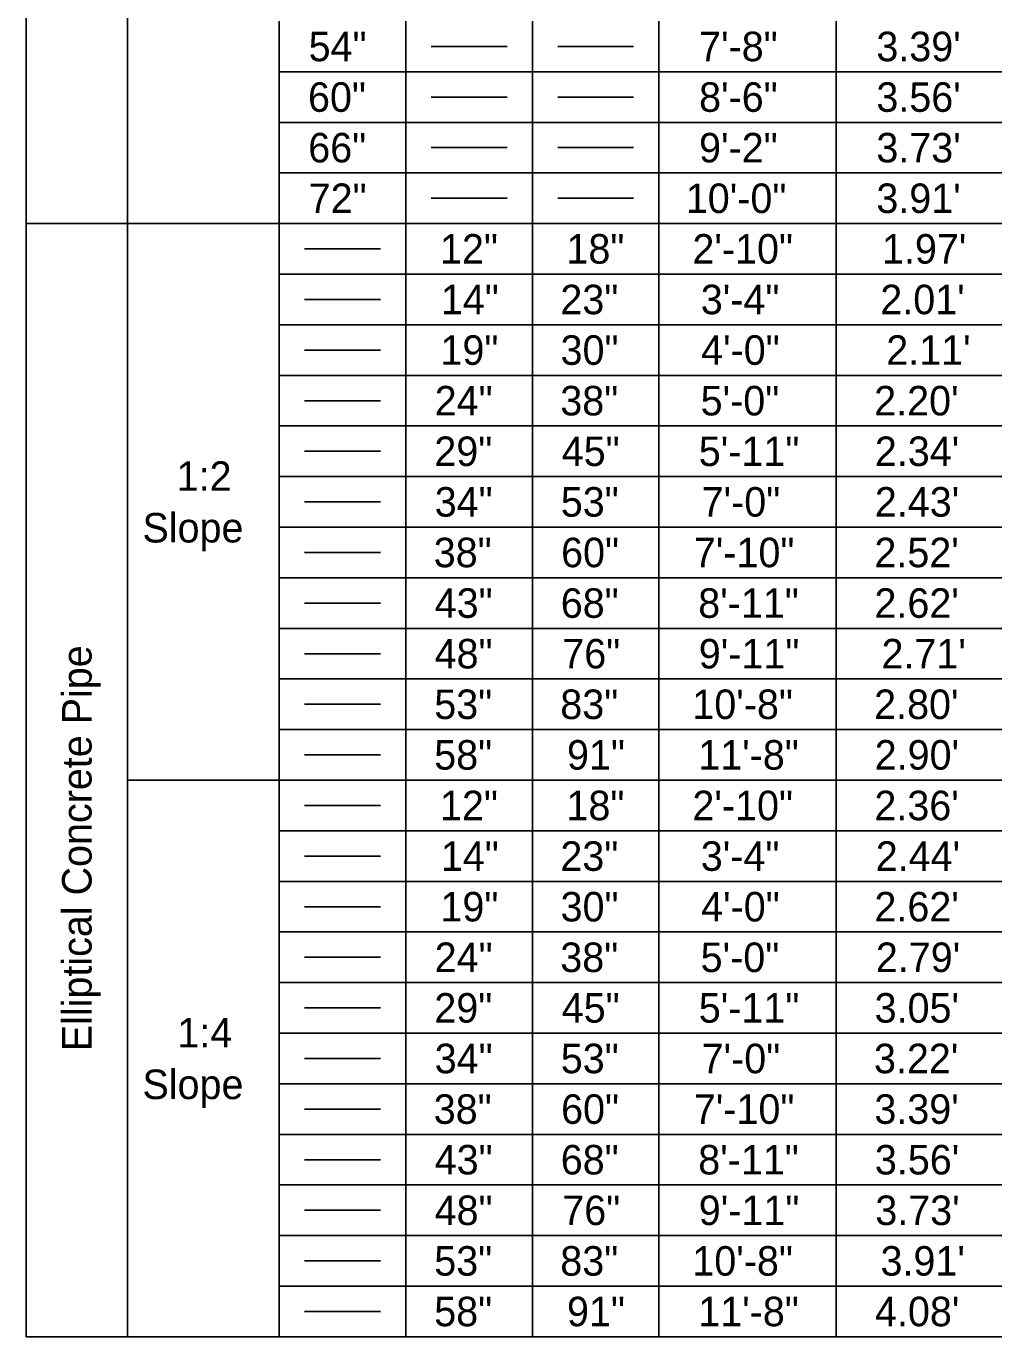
# Model space of a CAD drawing. Extents: x 1.7 to 14.6, y 0 to 8.4.
# Drawn here: x 1.7 to 3.994, y 2.19 to 5.298 of the extents above; entities that cross this region are included whole.
import ezdxf

# ---------------------------------------------------------------- set-up
doc = ezdxf.new("R2010")
doc.units = 0
doc.layers.add('Table', color=7, linetype='Continuous')

msp = doc.modelspace()

# ---------------------------------------------------------------- linework, layer by layer
at = {"layer": 'Table'}
for p, q in [((2.66, 5.25), (2.84, 5.25)), ((2.96, 5.25), (3.14, 5.25)), ((2.66, 5.13), (2.84, 5.13)), ((2.96, 5.13), (3.14, 5.13)), ((2.66, 5.01), (2.84, 5.01)), ((2.96, 5.01), (3.14, 5.01)), ((2.66, 4.89), (2.84, 4.89)), ((2.96, 4.89), (3.14, 4.89)), ((2.36, 4.77), (2.54, 4.77)), ((2.36, 4.65), (2.54, 4.65)), ((2.36, 4.53), (2.54, 4.53)), ((2.36, 4.41), (2.54, 4.41)), ((2.36, 4.29), (2.54, 4.29)), ((2.36, 4.17), (2.54, 4.17)), ((2.36, 4.05), (2.54, 4.05)), ((2.36, 3.93), (2.54, 3.93)), ((2.36, 3.81), (2.54, 3.81)), ((2.36, 3.69), (2.54, 3.69)), ((2.36, 3.57), (2.54, 3.57)), ((2.36, 3.45), (2.54, 3.45)), ((2.36, 3.33), (2.54, 3.33)), ((2.36, 3.21), (2.54, 3.21)), ((2.36, 3.09), (2.54, 3.09)), ((2.36, 2.97), (2.54, 2.97)), ((2.36, 2.85), (2.54, 2.85)), ((2.36, 2.73), (2.54, 2.73)), ((2.36, 2.61), (2.54, 2.61)), ((2.36, 2.49), (2.54, 2.49)), ((2.36, 2.37), (2.54, 2.37)), ((2.36, 2.25), (2.54, 2.25))]:
    msp.add_line(p, q, dxfattribs=at)
for points in [[(1.94, 8.43), (1.94, 7.83), (1.94, 7.47), (1.94, 6.15), (1.94, 4.83), (1.94, 3.51), (1.94, 2.19)], [(1.7, 7.47), (1.7, 4.83), (1.7, 2.19)], [(2.3, 5.31), (2.3, 5.19), (2.3, 5.07), (2.3, 4.95), (2.3, 4.83), (2.3, 4.71), (2.3, 4.59), (2.3, 4.47), (2.3, 4.35), (2.3, 4.23), (2.3, 4.11), (2.3, 3.99), (2.3, 3.87), (2.3, 3.75), (2.3, 3.63), (2.3, 3.51), (2.3, 3.39), (2.3, 3.27), (2.3, 3.15), (2.3, 3.03), (2.3, 2.91), (2.3, 2.79), (2.3, 2.67), (2.3, 2.55), (2.3, 2.43), (2.3, 2.31), (2.3, 2.19)], [(2.6, 5.31), (2.6, 5.19), (2.6, 5.07), (2.6, 4.95), (2.6, 4.83), (2.6, 4.71), (2.6, 4.59), (2.6, 4.47), (2.6, 4.35), (2.6, 4.23), (2.6, 4.11), (2.6, 3.99), (2.6, 3.87), (2.6, 3.75), (2.6, 3.63), (2.6, 3.51), (2.6, 3.39), (2.6, 3.27), (2.6, 3.15), (2.6, 3.03), (2.6, 2.91), (2.6, 2.79), (2.6, 2.67), (2.6, 2.55), (2.6, 2.43), (2.6, 2.31), (2.6, 2.19)], [(2.9, 5.31), (2.9, 5.19), (2.9, 5.07), (2.9, 4.95), (2.9, 4.83), (2.9, 4.71), (2.9, 4.59), (2.9, 4.47), (2.9, 4.35), (2.9, 4.23), (2.9, 4.11), (2.9, 3.99), (2.9, 3.87), (2.9, 3.75), (2.9, 3.63), (2.9, 3.51), (2.9, 3.39), (2.9, 3.27), (2.9, 3.15), (2.9, 3.03), (2.9, 2.91), (2.9, 2.79), (2.9, 2.67), (2.9, 2.55), (2.9, 2.43), (2.9, 2.31), (2.9, 2.19)], [(3.2, 5.31), (3.2, 5.19), (3.2, 5.07), (3.2, 4.95), (3.2, 4.83), (3.2, 4.71), (3.2, 4.59), (3.2, 4.47), (3.2, 4.35), (3.2, 4.23), (3.2, 4.11), (3.2, 3.99), (3.2, 3.87), (3.2, 3.75), (3.2, 3.63), (3.2, 3.51), (3.2, 3.39), (3.2, 3.27), (3.2, 3.15), (3.2, 3.03), (3.2, 2.91), (3.2, 2.79), (3.2, 2.67), (3.2, 2.55), (3.2, 2.43), (3.2, 2.31), (3.2, 2.19)], [(3.62, 5.31), (3.62, 5.19), (3.62, 5.07), (3.62, 4.95), (3.62, 4.83), (3.62, 4.71), (3.62, 4.59), (3.62, 4.47), (3.62, 4.35), (3.62, 4.23), (3.62, 4.11), (3.62, 3.99), (3.62, 3.87), (3.62, 3.75), (3.62, 3.63), (3.62, 3.51), (3.62, 3.39), (3.62, 3.27), (3.62, 3.15), (3.62, 3.03), (3.62, 2.91), (3.62, 2.79), (3.62, 2.67), (3.62, 2.55), (3.62, 2.43), (3.62, 2.31), (3.62, 2.19)], [(2.3, 5.19), (2.6, 5.19), (2.9, 5.19), (3.2, 5.19), (3.62, 5.19), (4.04, 5.19), (4.52, 5.19), (4.94, 5.19), (5.42, 5.19), (5.66, 5.19), (6.02, 5.19), (6.38, 5.19)], [(2.3, 5.07), (2.6, 5.07), (2.9, 5.07), (3.2, 5.07), (3.62, 5.07), (4.04, 5.07), (4.52, 5.07), (4.94, 5.07), (5.42, 5.07), (5.66, 5.07), (6.02, 5.07), (6.38, 5.07)], [(2.3, 4.95), (2.6, 4.95), (2.9, 4.95), (3.2, 4.95), (3.62, 4.95), (4.04, 4.95), (4.52, 4.95), (4.94, 4.95), (5.42, 4.95), (5.66, 4.95), (6.02, 4.95), (6.38, 4.95)], [(1.7, 4.83), (1.94, 4.83), (2.3, 4.83), (2.6, 4.83), (2.9, 4.83), (3.2, 4.83), (3.62, 4.83), (4.04, 4.83), (4.52, 4.83), (4.94, 4.83), (5.42, 4.83), (5.66, 4.83), (6.02, 4.83), (6.38, 4.83)], [(2.3, 4.71), (2.6, 4.71), (2.9, 4.71), (3.2, 4.71), (3.62, 4.71), (4.04, 4.71), (4.52, 4.71), (4.94, 4.71), (5.42, 4.71), (5.66, 4.71), (6.02, 4.71), (6.38, 4.71)], [(2.3, 4.59), (2.6, 4.59), (2.9, 4.59), (3.2, 4.59), (3.62, 4.59), (4.04, 4.59), (4.52, 4.59), (4.94, 4.59), (5.42, 4.59), (5.66, 4.59), (6.02, 4.59), (6.38, 4.59)], [(2.3, 4.47), (2.6, 4.47), (2.9, 4.47), (3.2, 4.47), (3.62, 4.47), (4.04, 4.47), (4.52, 4.47), (4.94, 4.47), (5.42, 4.47), (5.66, 4.47), (6.02, 4.47), (6.38, 4.47)], [(2.3, 4.35), (2.6, 4.35), (2.9, 4.35), (3.2, 4.35), (3.62, 4.35), (4.04, 4.35), (4.52, 4.35), (4.94, 4.35), (5.42, 4.35), (5.66, 4.35), (6.02, 4.35), (6.38, 4.35)], [(2.3, 4.23), (2.6, 4.23), (2.9, 4.23), (3.2, 4.23), (3.62, 4.23), (4.04, 4.23), (4.52, 4.23), (4.94, 4.23), (5.42, 4.23), (5.66, 4.23), (6.02, 4.23), (6.38, 4.23)], [(2.3, 4.11), (2.6, 4.11), (2.9, 4.11), (3.2, 4.11), (3.62, 4.11), (4.04, 4.11), (4.52, 4.11), (4.94, 4.11), (5.42, 4.11), (5.66, 4.11), (6.02, 4.11), (6.38, 4.11)], [(2.3, 3.99), (2.6, 3.99), (2.9, 3.99), (3.2, 3.99), (3.62, 3.99), (4.04, 3.99), (4.52, 3.99), (4.94, 3.99), (5.42, 3.99), (5.66, 3.99), (6.02, 3.99), (6.38, 3.99)], [(2.3, 3.87), (2.6, 3.87), (2.9, 3.87), (3.2, 3.87), (3.62, 3.87), (4.04, 3.87), (4.52, 3.87), (4.94, 3.87), (5.42, 3.87), (5.66, 3.87), (6.02, 3.87), (6.38, 3.87)], [(2.3, 3.75), (2.6, 3.75), (2.9, 3.75), (3.2, 3.75), (3.62, 3.75), (4.04, 3.75), (4.52, 3.75), (4.94, 3.75), (5.42, 3.75), (5.66, 3.75), (6.02, 3.75), (6.38, 3.75)], [(2.3, 3.63), (2.6, 3.63), (2.9, 3.63), (3.2, 3.63), (3.62, 3.63), (4.04, 3.63), (4.52, 3.63), (4.94, 3.63), (5.42, 3.63), (5.66, 3.63), (6.02, 3.63), (6.38, 3.63)], [(1.94, 3.51), (2.3, 3.51), (2.6, 3.51), (2.9, 3.51), (3.2, 3.51), (3.62, 3.51), (4.04, 3.51), (4.52, 3.51), (4.94, 3.51), (5.42, 3.51), (5.66, 3.51), (6.02, 3.51), (6.38, 3.51)], [(2.3, 3.39), (2.6, 3.39), (2.9, 3.39), (3.2, 3.39), (3.62, 3.39), (4.04, 3.39), (4.52, 3.39), (4.94, 3.39), (5.42, 3.39), (5.66, 3.39), (6.02, 3.39), (6.38, 3.39)], [(2.3, 3.27), (2.6, 3.27), (2.9, 3.27), (3.2, 3.27), (3.62, 3.27), (4.04, 3.27), (4.52, 3.27), (4.94, 3.27), (5.42, 3.27), (5.66, 3.27), (6.02, 3.27), (6.38, 3.27)], [(2.3, 3.15), (2.6, 3.15), (2.9, 3.15), (3.2, 3.15), (3.62, 3.15), (4.04, 3.15), (4.52, 3.15), (4.94, 3.15), (5.42, 3.15), (5.66, 3.15), (6.02, 3.15), (6.38, 3.15)], [(2.3, 3.03), (2.6, 3.03), (2.9, 3.03), (3.2, 3.03), (3.62, 3.03), (4.04, 3.03), (4.52, 3.03), (4.94, 3.03), (5.42, 3.03), (5.66, 3.03), (6.02, 3.03), (6.38, 3.03)], [(2.3, 2.91), (2.6, 2.91), (2.9, 2.91), (3.2, 2.91), (3.62, 2.91), (4.04, 2.91), (4.52, 2.91), (4.94, 2.91), (5.42, 2.91), (5.66, 2.91), (6.02, 2.91), (6.38, 2.91)], [(2.3, 2.79), (2.6, 2.79), (2.9, 2.79), (3.2, 2.79), (3.62, 2.79), (4.04, 2.79), (4.52, 2.79), (4.94, 2.79), (5.42, 2.79), (5.66, 2.79), (6.02, 2.79), (6.38, 2.79)], [(2.3, 2.67), (2.6, 2.67), (2.9, 2.67), (3.2, 2.67), (3.62, 2.67), (4.04, 2.67), (4.52, 2.67), (4.94, 2.67), (5.42, 2.67), (5.66, 2.67), (6.02, 2.67), (6.38, 2.67)], [(2.3, 2.55), (2.6, 2.55), (2.9, 2.55), (3.2, 2.55), (3.62, 2.55), (4.04, 2.55), (4.52, 2.55), (4.94, 2.55), (5.42, 2.55), (5.66, 2.55), (6.02, 2.55), (6.38, 2.55)], [(2.3, 2.43), (2.6, 2.43), (2.9, 2.43), (3.2, 2.43), (3.62, 2.43), (4.04, 2.43), (4.52, 2.43), (4.94, 2.43), (5.42, 2.43), (5.66, 2.43), (6.02, 2.43), (6.38, 2.43)], [(2.3, 2.31), (2.6, 2.31), (2.9, 2.31), (3.2, 2.31), (3.62, 2.31), (4.04, 2.31), (4.52, 2.31), (4.94, 2.31), (5.42, 2.31), (5.66, 2.31), (6.02, 2.31), (6.38, 2.31)], [(1.7, 2.19), (1.94, 2.19), (2.3, 2.19), (2.6, 2.19), (2.9, 2.19), (3.2, 2.19), (3.62, 2.19), (4.04, 2.19), (4.52, 2.19), (4.94, 2.19), (5.42, 2.19), (5.66, 2.19), (6.02, 2.19), (6.38, 2.19)]]:
    msp.add_lwpolyline(points, dxfattribs=at)

# ---------------------------------------------------------------- texts
for s, rotation, p in [('54"', 0, (2.3695, 5.215)), ('7\'-8"', 0, (3.2951, 5.215)), ("3.39'", 0, (3.7154, 5.215)), ('60"', 0, (2.368, 5.095)), ('8\'-6"', 0, (3.2951, 5.095)), ("3.56'", 0, (3.7154, 5.095)), ('66"', 0, (2.3686, 4.975)), ('9\'-2"', 0, (3.2951, 4.975)), ("3.73'", 0, (3.7154, 4.975)), ('72"', 0, (2.3697, 4.855)), ('10\'-0"', 0, (3.2637, 4.855)), ("3.91'", 0, (3.7154, 4.855)), ('12"', 0, (2.6809, 4.735)), ('18"', 0, (2.9807, 4.735)), ('2\'-10"', 0, (3.2793, 4.735)), ("1.97'", 0, (3.7287, 4.735)), ('14"', 0, (2.683, 4.615)), ('23"', 0, (2.9663, 4.615)), ('3\'-4"', 0, (3.2992, 4.615)), ("2.01'", 0, (3.7248, 4.615)), ('19"', 0, (2.682, 4.495)), ('30"', 0, (2.9668, 4.495)), ('4\'-0"', 0, (3.2999, 4.495)), ("2.11'", 0, (3.7388, 4.495)), ('24"', 0, (2.6684, 4.375)), ('38"', 0, (2.9661, 4.375)), ('5\'-0"', 0, (3.2988, 4.375)), ("2.20'", 0, (3.7103, 4.375)), ('29"', 0, (2.6675, 4.255)), ('45"', 0, (2.9695, 4.255)), ('5\'-11"', 0, (3.2944, 4.255)), ("2.34'", 0, (3.7118, 4.255)), ('34"', 0, (2.6684, 4.135)), ('53"', 0, (2.9673, 4.135)), ('7\'-0"', 0, (3.3011, 4.135)), ("2.43'", 0, (3.7118, 4.135)), ('38"', 0, (2.6661, 4.015)), ('60"', 0, (2.968, 4.015)), ('7\'-10"', 0, (3.2827, 4.015)), ("2.52'", 0, (3.7108, 4.015)), ('43"', 0, (2.6684, 3.895)), ('68"', 0, (2.9672, 3.895)), ('8\'-11"', 0, (3.2931, 3.895)), ("2.62'", 0, (3.7109, 3.895)), ('Elliptical Concrete Pipe', 90, (1.855, 2.8673)), ('48"', 0, (2.6682, 3.775)), ('76"', 0, (2.9708, 3.775)), ('9\'-11"', 0, (3.2944, 3.775)), ("2.71'", 0, (3.7276, 3.775)), ('53"', 0, (2.6673, 3.655)), ('83"', 0, (2.9661, 3.655)), ('10\'-8"', 0, (3.2791, 3.655)), ("2.80'", 0, (3.7101, 3.655)), ('58"', 0, (2.6672, 3.535)), ('91"', 0, (2.982, 3.535)), ('11\'-8"', 0, (3.2931, 3.535)), ("2.90'", 0, (3.7114, 3.535)), ('12"', 0, (2.6809, 3.415)), ('18"', 0, (2.9807, 3.415)), ('2\'-10"', 0, (3.2793, 3.415)), ("2.36'", 0, (3.7108, 3.415)), ('14"', 0, (2.683, 3.295)), ('23"', 0, (2.9663, 3.295)), ('3\'-4"', 0, (3.2992, 3.295)), ("2.44'", 0, (3.7139, 3.295)), ('19"', 0, (2.682, 3.175)), ('30"', 0, (2.9668, 3.175)), ('4\'-0"', 0, (3.2999, 3.175)), ("2.62'", 0, (3.7109, 3.175)), ('24"', 0, (2.6684, 3.055)), ('38"', 0, (2.9661, 3.055)), ('5\'-0"', 0, (3.2988, 3.055)), ("2.79'", 0, (3.7142, 3.055)), ('29"', 0, (2.6675, 2.935)), ('45"', 0, (2.9695, 2.935)), ('5\'-11"', 0, (3.2944, 2.935)), ("3.05'", 0, (3.7113, 2.935)), ('34"', 0, (2.6684, 2.815)), ('53"', 0, (2.9673, 2.815)), ('7\'-0"', 0, (3.3011, 2.815)), ("3.22'", 0, (3.7097, 2.815)), ('38"', 0, (2.6661, 2.695)), ('60"', 0, (2.968, 2.695)), ('7\'-10"', 0, (3.2827, 2.695)), ("3.39'", 0, (3.7107, 2.695)), ('43"', 0, (2.6684, 2.575)), ('68"', 0, (2.9672, 2.575)), ('8\'-11"', 0, (3.2931, 2.575)), ("3.56'", 0, (3.7119, 2.575)), ('48"', 0, (2.6682, 2.455)), ('76"', 0, (2.9708, 2.455)), ('9\'-11"', 0, (3.2944, 2.455)), ("3.73'", 0, (3.7129, 2.455)), ('53"', 0, (2.6673, 2.335)), ('83"', 0, (2.9661, 2.335)), ('10\'-8"', 0, (3.2791, 2.335)), ("3.91'", 0, (3.7253, 2.335)), ('58"', 0, (2.6672, 2.215)), ('91"', 0, (2.982, 2.215)), ('11\'-8"', 0, (3.2931, 2.215)), ("4.08'", 0, (3.7122, 2.215))]:
    msp.add_text(s, height=0.07, rotation=rotation, dxfattribs=at).set_placement(p)
for s, p in [('1:2', (2.0566, 4.1962)), ('Slope', (1.9756, 4.0737)), ('1:4', (2.0583, 2.8762)), ('Slope', (1.9756, 2.7537))]:
    msp.add_text(s, height=0.07, dxfattribs=at).set_placement(p)

doc.saveas('drawing.dxf')
